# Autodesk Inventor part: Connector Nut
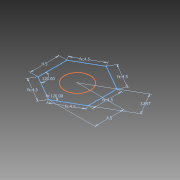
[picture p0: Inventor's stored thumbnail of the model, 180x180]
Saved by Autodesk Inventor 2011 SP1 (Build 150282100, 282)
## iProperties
Created: 2011-10
Part Number: Connector Nut
Document SubType Name: Modeling
Designer: sdarley
Density: 1 g/cm^3
Author: sdarley
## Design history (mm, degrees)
sketch "Sketch1"
  geometry: L1 (-3.897, -2.25)-(-3.897, 2.25); L2 (3.897, -2.25)-(3.897, 2.25); L3 (-3.897, -2.25)-(0, -4.5); L4 (0, -4.5)-(3.897, -2.25); L5 (3.897, 2.25)-(0, 4.5); L6 (0, 4.5)-(-3.897, 2.25); L7 (-3.897, 2.25)-(0, 4.5); L8 (3.897, 2.25)-(3.897, -2.25); L9 (3.897, -2.25)-(0, -4.5); L10 (0, -4.5)-(-3.897, -2.25); L11 (-3.897, -2.25)-(-3.897, 2.25); L12 (0, 4.5)-(3.897, 2.25); C1 r 2 at (0, 0) reference; C2 r 2.625 at (0, 0)
  constraints: 24 end point, 8 equal length, 1 centre point, 1 coincident, 1 vertical
  dimensions: "d31" = 5.25 diameter of C2
extrude "Extrusion2" new body sketch "Sketch1" distance "d32" = 2; taper "d33" = 0 deg
thread "Thread2" dims "d34" = 10, "d35" = 0
workplane "Work Plane1"
sketch "Sketch2"
  geometry: L1 (0, -2.25)-(0, 0) reference; L2 (-2, 0)-(0, 0) reference; L3 (-2, 1)-(-2, -10) reference; L4 (0, -0.581)-(-0.211, 0); L5 (-1.78, 0)-(-2, -0.604); L6 (-1.78, 0)-(-2, 0); L7 (-2, 0)-(-2, -0.604); L8 (-0.211, 0)-(0, 0); L9 (0, 0)-(0, -0.581); L10 (2.579, -4.5)-(-3.807, -4.5); 1 further point
  constraints: 14 end point, 4 point on line, 2 collinear, 1 perpendicular
  dimensions: "d36" = 160 deg angle of L1 L4; "d37" = 160 deg angle of L3 L5 (= d36)
  node "Reference2"
revolve "Revolution1" stored, may be unused: angle "d38" = 90 deg
body "Solid2"
node "Reference1"
